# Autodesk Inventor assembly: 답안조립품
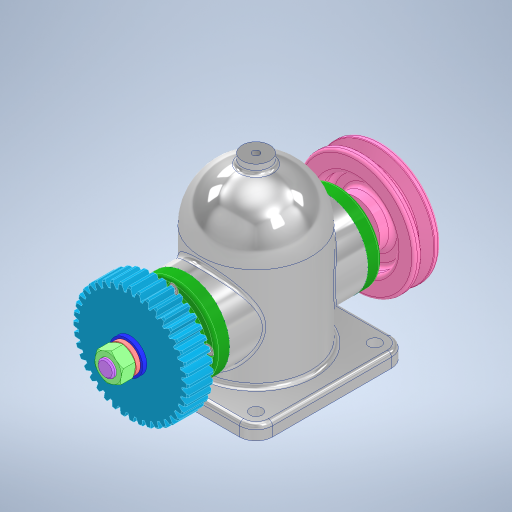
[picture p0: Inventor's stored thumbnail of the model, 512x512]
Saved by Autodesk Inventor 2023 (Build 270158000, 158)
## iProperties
Created: 2025-04
Part Number: 답안조립품
Document SubType Name: Assembly
Designer: user
Author: user
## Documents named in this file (14)
- C:\Users\user\Desktop\750406V1011\답안조립품.iam
- C:\Users\user\Desktop\750406V1011\본체.ipt
- C:\Users\user\Desktop\750406V1011\깊은 홈 볼 베어링 6203.ipt
- C:\Users\user\Desktop\750406V1011\축.ipt
- C:\Users\user\Desktop\750406V1011\커버.ipt
- C:\Users\user\Desktop\750406V1011\오일 실 26 38 8.ipt
- C:\Users\user\Desktop\750406V1011\6각 구멍붙이 볼트 M4x12.ipt
- C:\Users\user\Desktop\750406V1011\칼라.ipt
- C:\Users\user\Desktop\750406V1011\평행 키 5x5x12.ipt
- C:\Users\user\Desktop\750406V1011\스퍼기어.ipt
- C:\Users\user\Desktop\750406V1011\V 벨트 풀리.ipt
- C:\Users\user\Desktop\750406V1011\평와셔 M12.ipt
- C:\Users\user\Desktop\750406V1011\스프링 와셔 M12.ipt
- C:\Users\user\Desktop\750406V1011\6각 너트 M12x1.ipt
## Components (11 placed, 3 different names)
1. 6각 구멍붙이 볼트 M4x12:1
2. 6각 구멍붙이 볼트 M4x12:2
3. 6각 구멍붙이 볼트 M4x12:3
4. 6각 구멍붙이 볼트 M4x12:4
5. 6각 구멍붙이 볼트 M4x12:5
6. 6각 구멍붙이 볼트 M4x12:6
7. 6각 구멍붙이 볼트 M4x12:7
8. 6각 구멍붙이 볼트 M4x12:8
9. V 벨트 풀리:1
10. 6각 너트 M12x1:2
11. 6각 너트 M12x1:3
